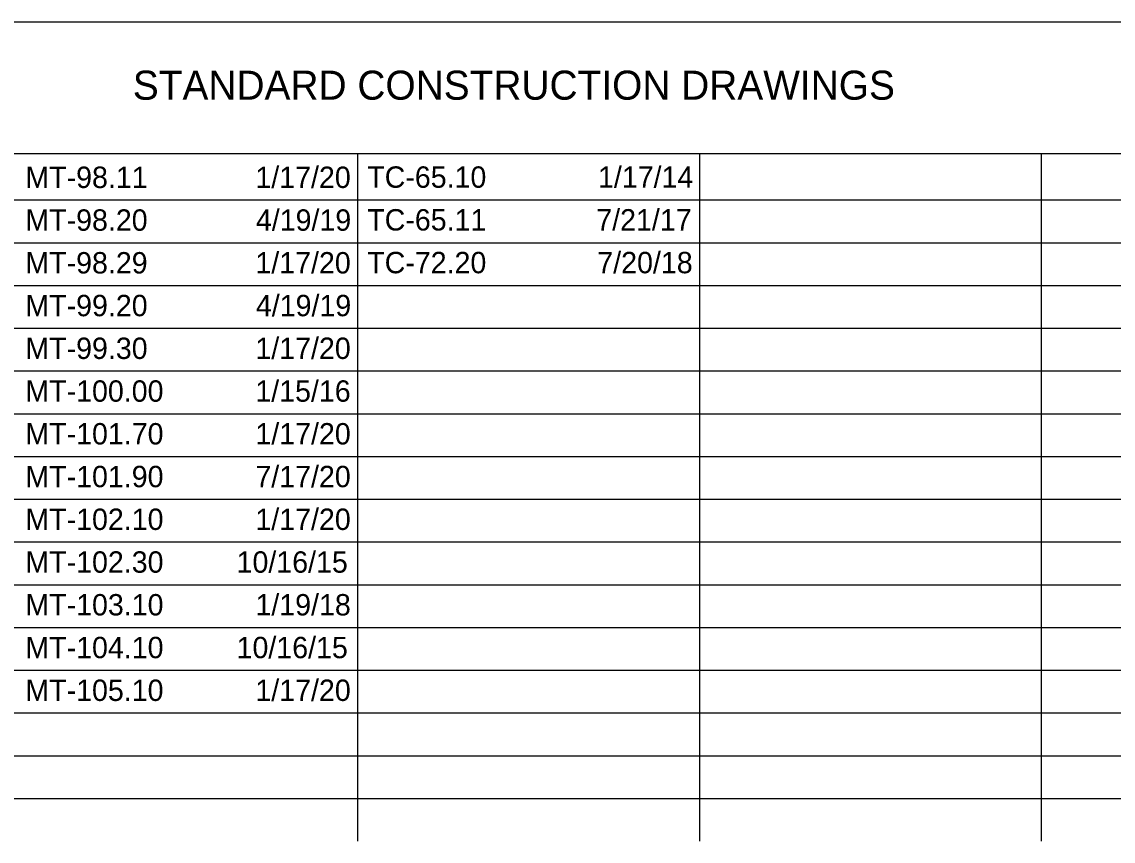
# Model space of a CAD drawing. Extents: x 2080852 to 2433556, y 1080825 to 1306626.
# Drawn here: x 2217967 to 2285387, y 1086105 to 1136706 of the extents above; entities that cross this region are included whole.
import ezdxf

# ---------------------------------------------------------------- set-up
doc = ezdxf.new("R2010")
doc.units = 0
doc.layers.add('PM_P_Lane_Line', color=7, linetype='Continuous')

msp = doc.modelspace()

# ---------------------------------------------------------------- linework, layer by layer
at = {"layer": 'PM_P_Lane_Line'}
for p, q in [((2196484, 1136706), (2338516, 1136706)), ((2196484, 1128566), (2338516, 1128566)), ((2238724, 1086105), (2238724, 1128566)), ((2259844, 1086105), (2259844, 1128566)), ((2280964, 1086105), (2280964, 1128566)), ((2196484, 1125705), (2338516, 1125705)), ((2196484, 1123065), (2338516, 1123065)), ((2196484, 1120425), (2338516, 1120425)), ((2196484, 1117785), (2338516, 1117785)), ((2196484, 1115145), (2338516, 1115145)), ((2196484, 1112505), (2338516, 1112505)), ((2196484, 1109865), (2338516, 1109865)), ((2196484, 1107225), (2338516, 1107225)), ((2196484, 1104585), (2338516, 1104585)), ((2196484, 1101945), (2338516, 1101945)), ((2196484, 1099305), (2338516, 1099305)), ((2196484, 1096665), (2338516, 1096665)), ((2196484, 1094025), (2338516, 1094025)), ((2196484, 1091385), (2338516, 1091385)), ((2196484, 1088745), (2338516, 1088745))]:
    msp.add_line(p, q, dxfattribs=at)

# ---------------------------------------------------------------- texts
for s, height, p in [('STANDARD CONSTRUCTION DRAWINGS', 1795.2, (2224825, 1131896)), ('MT-98.11', 1320, (2218185, 1126444)), ('1/17/20', 1320, (2232397, 1126444)), ('TC-65.10', 1320, (2239305, 1126458)), ('1/17/14', 1320, (2253561, 1126458)), ('MT-98.20', 1320, (2218185, 1123804)), ('4/19/19', 1320, (2232427, 1123804)), ('TC-65.11', 1320, (2239305, 1123818)), ('7/21/17', 1320, (2253455, 1123818)), ('1/17/20', 1320, (2232397, 1121164)), ('7/20/18', 1320, (2253520, 1121178)), ('MT-98.29', 1320, (2218185, 1121164)), ('TC-72.20', 1320, (2239305, 1121178)), ('MT-99.20', 1320, (2218185, 1118524)), ('4/19/19', 1320, (2232427, 1118524)), ('MT-99.30', 1320, (2218185, 1115884)), ('1/17/20', 1320, (2232397, 1115884)), ('MT-100.00', 1320, (2218185, 1113244)), ('1/15/16', 1320, (2232393, 1113244)), ('MT-101.70', 1320, (2218185, 1110604)), ('1/17/20', 1320, (2232397, 1110604)), ('MT-101.90', 1320, (2218185, 1107964)), ('7/17/20', 1320, (2232397, 1107964)), ('MT-102.10', 1320, (2218185, 1105324)), ('1/17/20', 1320, (2232397, 1105324)), ('MT-102.30', 1320, (2218185, 1102684)), ('10/16/15', 1320, (2231235, 1102684)), ('MT-103.10', 1320, (2218185, 1100044)), ('1/19/18', 1320, (2232400, 1100044)), ('MT-104.10', 1320, (2218185, 1097404)), ('10/16/15', 1320, (2231235, 1097404)), ('MT-105.10', 1320, (2218185, 1094764)), ('1/17/20', 1320, (2232397, 1094764))]:
    msp.add_text(s, height=height, dxfattribs=at).set_placement(p)

doc.saveas('drawing.dxf')
